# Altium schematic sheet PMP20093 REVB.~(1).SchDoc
size 431 x 279 mm; Date: Not shown in title block; ApprovedBy: Not shown in title block; CheckedBy: Not shown in title block; Author: Not shown in title block; CompanyName: Not shown in title block; Engineer: Not shown in title block; Organization: Not shown in title block; Address1: Not shown in title block; Address2: Not shown in title block; Address3: Not shown in title block; Address4: Not shown in title block; DocumentNumber: 1; Revision: Use project parameter SCH_Rev; SheetNumber: 2; SheetTotal: 3; PageSetup: Record=PageOptions¦CenterHorizontal=True¦CenterVertical=True¦PrintScale=1.00¦XCorrection=1.00¦YCorrection=1.00¦PrintKind=0¦BorderSize=5000000¦LeftOffset=0¦BottomOffset=0¦Orientation=2¦PaperLength=1000¦PaperWidth=1000¦Scale=100¦PaperSource=15¦PrintQuality=600¦MediaType=1¦DitherType=10¦PaperKind=Letter¦PrintScaleMode=1
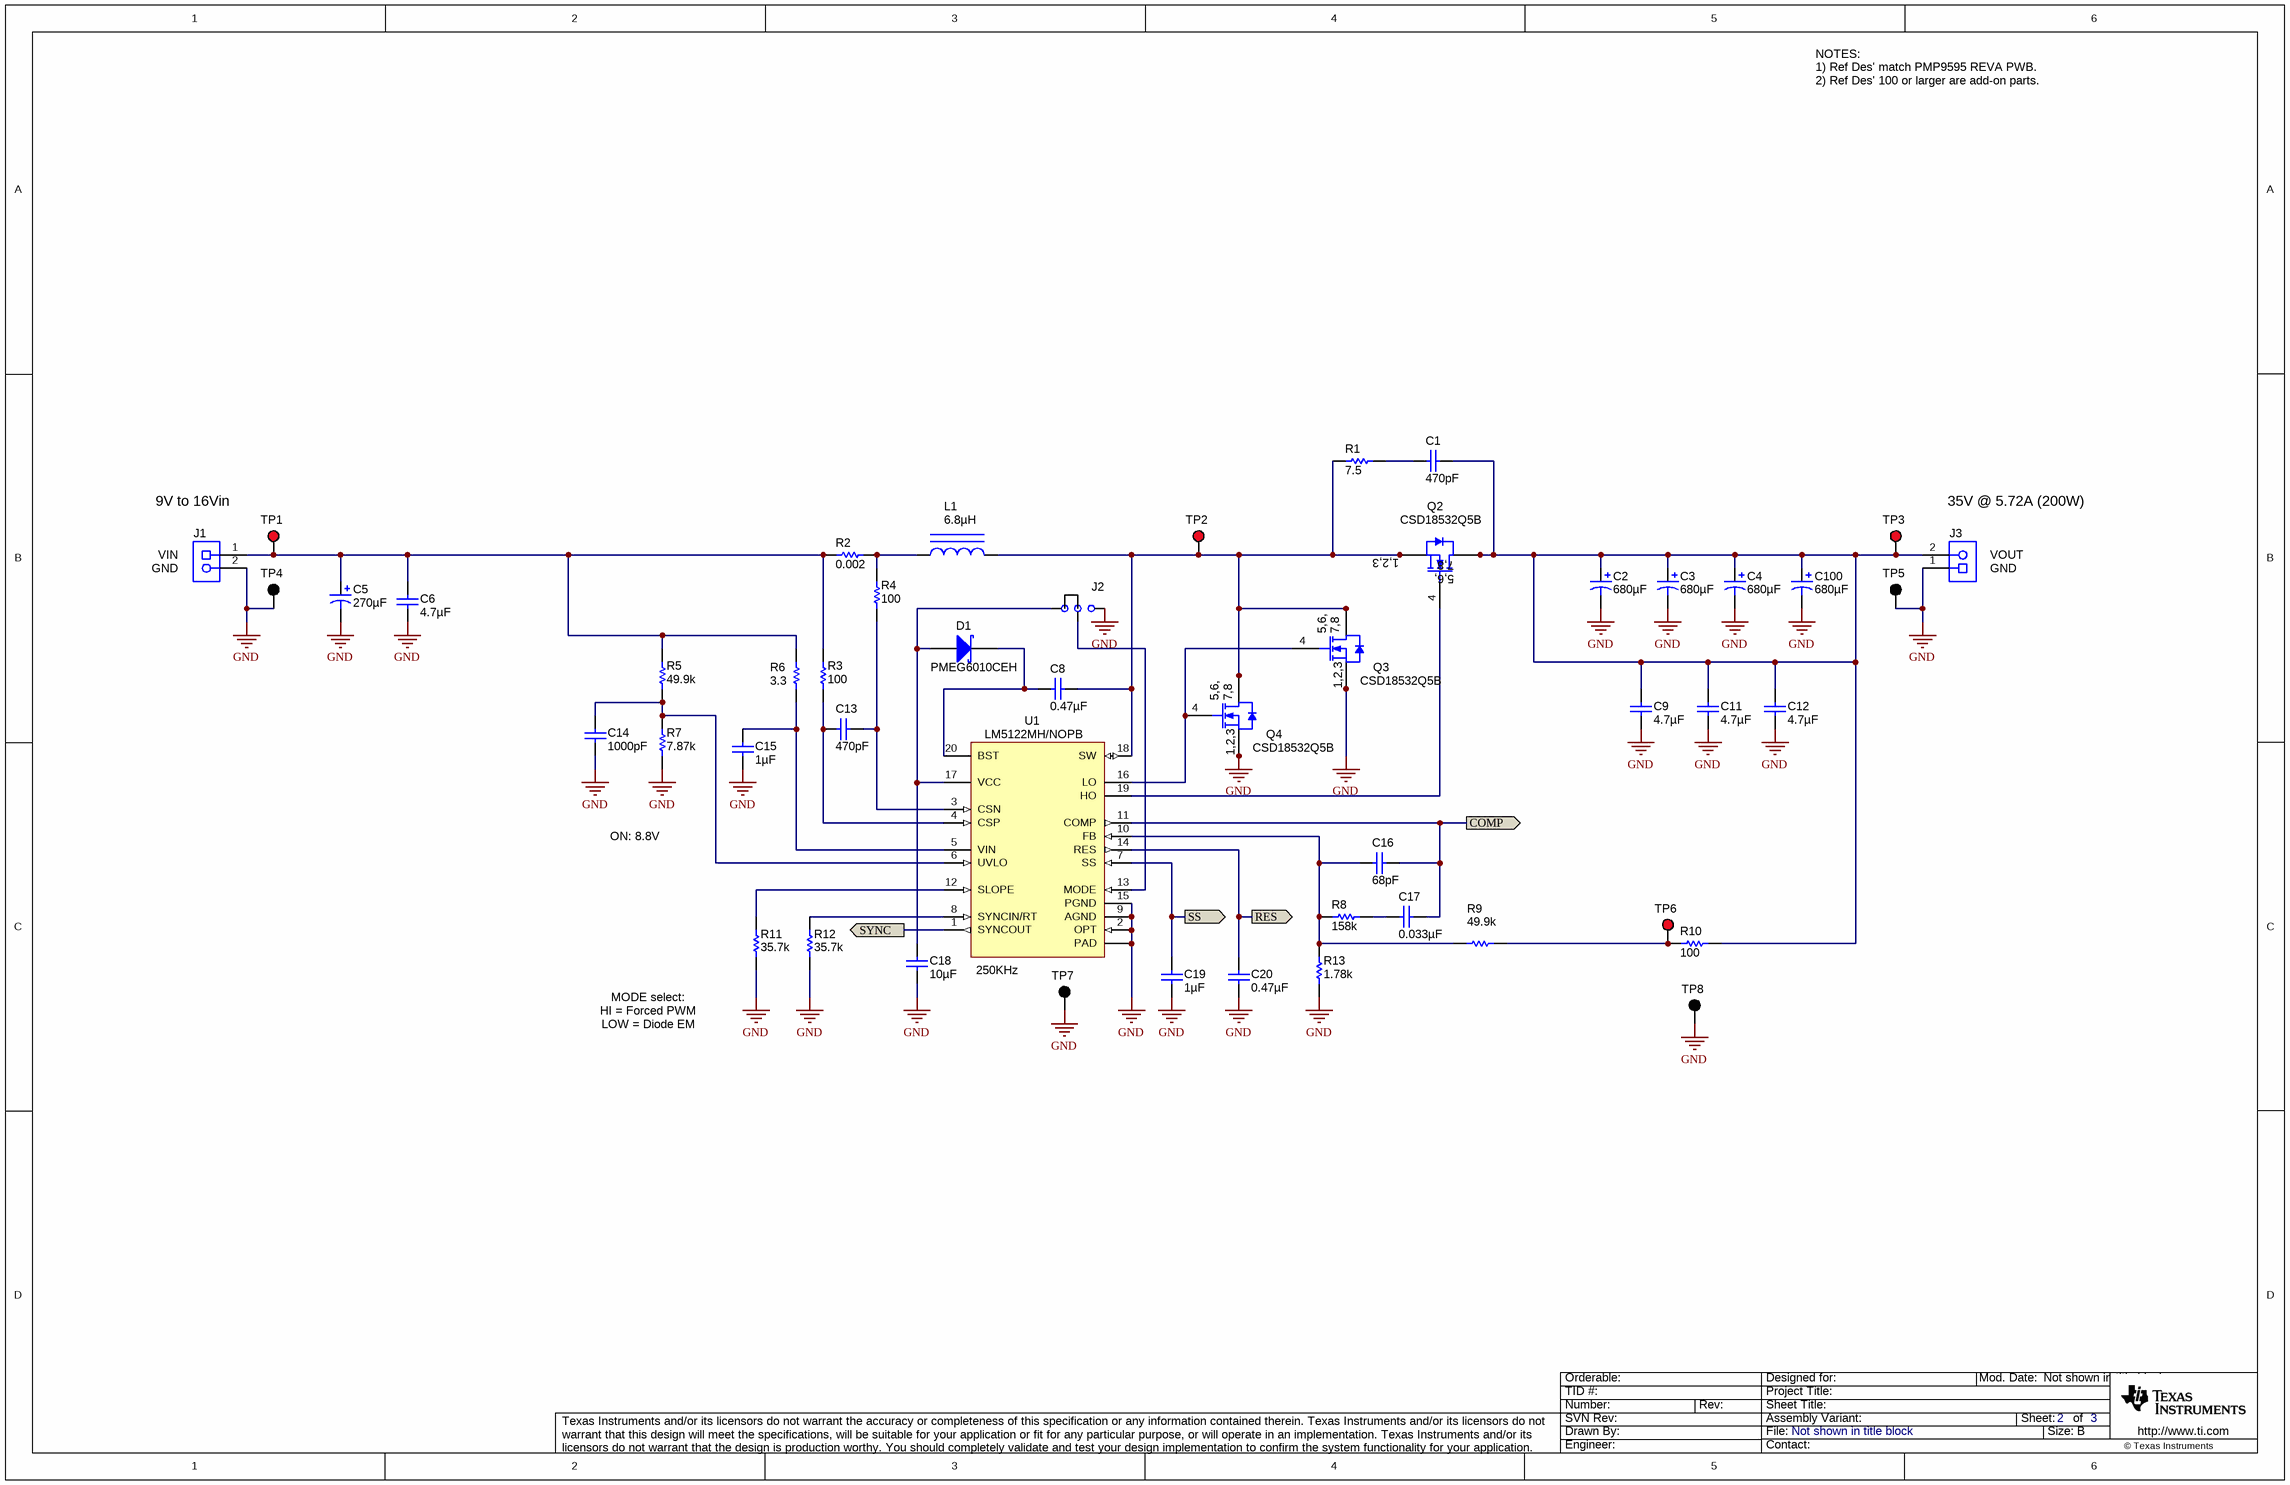
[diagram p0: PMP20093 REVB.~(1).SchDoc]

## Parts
C1  ValueDisplayed: 470pF  [0603]  (hidden comment: C1608C0G1H471J)
C2  ValueDisplayed: 680µF  [ZL_1250x2500]  (hidden comment: 50ZL680MEFC12.5X25)
C3  ValueDisplayed: 680µF  [ZL_1250x2500]  (hidden comment: 50ZL680MEFC12.5X25)
C4  ValueDisplayed: 680µF  [ZL_1250x2500]  (hidden comment: 50ZL680MEFC12.5X25)
C5  ValueDisplayed: 270µF  [SM_RADIAL_10BMM]  (hidden comment: EEHZA1V271P)
C6  ValueDisplayed: 4.7µF  [1210]  (hidden comment: GRM32ER71H475KA88L)
C8  ValueDisplayed: 0.47µF  [0603]  (hidden comment: GRM188R71E474KA12D)
C9  ValueDisplayed: 4.7µF  [1210]  (hidden comment: GRM32ER71H475KA88L)
C11  ValueDisplayed: 4.7µF  [1210]  (hidden comment: GRM32ER71H475KA88L)
C12  ValueDisplayed: 4.7µF  [1210]  (hidden comment: GRM32ER71H475KA88L)
C13  ValueDisplayed: 470pF  [0603]  (hidden comment: C1608C0G1H471J)
C14  ValueDisplayed: 1000pF  [0603]  (hidden comment: GRM188R71H102KA01D)
C15  ValueDisplayed: 1µF  [1206]  (hidden comment: C3216X7R1H105K)
C16  ValueDisplayed: 68pF  [0603]  (hidden comment: C1608C0G1H680J)
C17  ValueDisplayed: 0.033µF  [0603]  (hidden comment: C1608X7R1H333K)
C18  ValueDisplayed: 10µF  [1206]  (hidden comment: C3216X7R1E106K)
C19  ValueDisplayed: 1µF  [0603]  (hidden comment: C1608X7R1E105K080AB)
C20  ValueDisplayed: 0.47µF  [0603]  (hidden comment: GRM188R71E474KA12D)
C100  ValueDisplayed: 680µF  [ZL_1250x2500]  (hidden comment: 50ZL680MEFC12.5X25)
D1  PMEG6010CEH  [SOD-123F]
J1  ED120/2DS  [CONN_ED120-2DS]  (value not drawn)
J2  JUMPER_3X100MIL  [HDR100_1X3]  (value not drawn)
J3  ED120/2DS  [CONN_ED120-2DS]  (value not drawn)
L1  ValueDisplayed: 6.8µH  [IHLP8787MZ]  (hidden comment: IHLP8787MZER6R8M5A)
Q2  CSD18532Q5B  [TRANS_NexFET_Q5B]
Q3  CSD18532Q5B  [TRANS_NexFET_Q5B]
Q4  CSD18532Q5B  [TRANS_NexFET_Q5B]
R1  value 7.5  [2010M]  (hidden comment: CRM2010-JW-7R5ELF)
R2  value 0.002  [2512]  (hidden comment: CSNL2512FT2L00)
R3  value 100  [0603_HV]  (hidden comment: ERJ-3GEY0R00V)
R4  value 100  [0603_HV]  (hidden comment: ERJ-3GEY0R00V)
R5  value 49.9k  [0603]  (hidden comment: CRCW060349K9FKEA)
R6  value 3.3  [0603_HV]  (hidden comment: CRCW06033R30JNEA)
R7  ValueDisplayed: 7.87k  [0603]  (hidden comment: CRCW06037K87FKEA)
R8  ValueDisplayed: 158k  [0603]  (hidden comment: CRCW0603158KFKEA)
R9  value 49.9k  [0603]  (hidden comment: CRCW060349K9FKEA)
R10  value 100  [0603]  (hidden comment: CRCW0603100RFKEA)
R11  ValueDisplayed: 35.7k  [0603]  (hidden comment: CRCW060335K7FKEA)
R12  ValueDisplayed: 35.7k  [0603]  (hidden comment: CRCW060335K7FKEA)
R13  ValueDisplayed: 1.78k  [0603]  (hidden comment: CRCW06031K78FKEA)
TP1  5010  [Keystone5010]  (value not drawn)
TP2  5010  [Keystone5010]  (value not drawn)
TP3  5010  [Keystone5010]  (value not drawn)
TP4  5011  [Keystone5011]  (value not drawn)
TP5  5011  [Keystone5011]  (value not drawn)
TP6  5010  [Keystone5010]  (value not drawn)
TP7  5011  [Keystone5011]  (value not drawn)
TP8  5011  [Keystone5011]  (value not drawn)
U1  LM5122MH/NOPB  [PWP0020A_N]

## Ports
COMP, RES, SS, SYNC

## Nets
GND: C2.2(-) C3.2(-) C4.2(-) C5.2(-) C6.2 C9.2 C11.2 C12.2 C14.2 C15.2 C18.2 C19.2 C20.1 C100.2(-) J1.2 J2.1 J3.1 Q3.1(S) Q3.2(S) Q3.3(S) Q4.1(S) Q4.2(S) Q4.3(S) R7.1 R11.1 R12.1 R13.1 TP4.1 TP5.1 TP7.1 TP8.1 U1.2(OPT) U1.9(AGND) U1.15(PGND) U1.21(PAD)
COMP: C16.2 C17.2 U1.11(COMP) ; port COMP
RES: C20.2 U1.14(RES) ; port RES
SS: C19.1 U1.7(SS) ; port SS
SYNC: U1.1(SYNCOUT) ; port SYNC
NetC1_1: C1.1 C2.1(+) C3.1(+) C4.1(+) C9.1 C11.1 C12.1 C100.1(+) J3.2 Q2.5(D) Q2.6(D) Q2.7(D) Q2.8(D) R10.2 TP3.1
NetC1_2: C1.2 R1.2
NetC5_1: C5.1(+) C6.1 J1.1 R2.1 R3.2 R5.2 R6.1 TP1.1
NetC8_1: C8.1 D1.1(K) U1.20(BST)
NetC8_2: C8.2 L1.2 Q2.1(S) Q2.2(S) Q2.3(S) Q3.5(D) Q3.6(D) Q3.7(D) Q3.8(D) Q4.5(D) Q4.6(D) Q4.7(D) Q4.8(D) R1.1 TP2.1 U1.18(SW)
NetC13_1: C13.1 R4.1 U1.3(CSN)
NetC13_2: C13.2 R3.1 U1.4(CSP)
NetC14_1: C14.1 R5.1 R7.2 U1.6(UVLO)
NetC15_1: C15.1 R6.2 U1.5(VIN)
NetC16_1: C16.1 R8.1 R9.1 R13.2 U1.10(FB)
NetC17_1: C17.1 R8.2
NetC18_1: C18.1 D1.2(A) J2.3 U1.17(VCC)
NetJ2_2: J2.2 U1.13(MODE)
NetL1_1: L1.1 R2.2 R4.2
NetQ2_4: Q2.4(G) U1.19(HO)
NetQ3_4: Q3.4(G) Q4.4(G) U1.16(LO)
NetR9_2: R9.2 R10.1 TP6.1
NetR11_2: R11.2 U1.12(SLOPE)
NetR12_2: R12.2 U1.8(SYNCIN/RT)

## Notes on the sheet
- NOTES:
  1) Ref Des' match PMP9595 REVA PWB.
  2) Ref Des' 100 or larger are add-on parts.
- 9V to 16Vin
- 35V @ 5.72A (200W)
- (near J1) VIN
- (near J1) GND
- (near J3) VOUT
- (near J3) GND
- ON: 8.8V
- (near U1) 250KHz
- MODE select:
- HI = Forced PWM
- LOW = Diode EM

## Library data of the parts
C1 C13 = C1608C0G1H471J: CAP, CERM, 470pF, 50V, +/-5%, C0G/NP0, 0603; Manufacturer: TDK; Polarized: N; CompType: Capacitor; U/M: EA; Cap_F: 0.00000000047; Tolerance_%: 5; ESR_Ohm: 0.0922; Value1: 0.0922 ohm; VDC_V: 50; TaMin_C: -55; TaMax_C: 125
C2-C4 C100 = 50ZL560MEFC12.5X25: CAP, AL, 680 µF, 50 V, +/- 20%, 2.86A, 0.021 ohm, TH; Manufacturer: Rubycon; Polarized: Y; CompType: Capacitor; Value: 680uF; U/M: EA; Cap_F: 0.00056; Tolerance_%: 20; VDC_V: 50; Value2: 50V; ESR_ohm: 0.023; IRMS_A: 2.41; TaMin_C: -40; TaMax_C: 105; Cap_Case: 12.5x25mm; AEC Category: Q200; AEC Qualified: N
C5 = EEHZA1V271P: CAP, Polymer Hybrid, 270 µF, 35 V, +/- 20%, 20 ohm, 10x10 SMD; Manufacturer: Panasonic; Polarized: Y; CompType: Capacitor; Value: 270uF; U/M: EA; Cap_F: 0.00027; Tolerance_%: 20; Value1: 20 ohm; VDC_V: 35; Value2: 35V; IRMS_A: 2.5; TaMin_C: -55; TaMax_C: 105; AEC Category: Q200
C6 C9 C11 C12 = GRM32ER71H475KA88L: CAP, CERM, 4.7uF, 50V, +/-10%, X7R, 1210; Manufacturer: MuRata; Polarized: N; CompType: Capacitor; U/M: EA; Cap_F: 0.0000047; Tolerance_%: 10; ESR_Ohm: 0.002; Value1: 0.002 ohm; VDC_V: 50; TaMin_C: -55; TaMax_C: 125
C8 C20 = GRM188R71E474KA12D: CAP, CERM, 0.47uF, 25V, +/-10%, X7R, 0603; Manufacturer: MuRata; Polarized: N; CompType: Capacitor; U/M: EA; Cap_F: 0.00000047; Tolerance_%: 10; Value1: Unknown; VDC_V: 25; TaMin_C: -55; TaMax_C: 125
C14 = GRM188R71H102KA01D: CAP, CERM, 1000pF, 50V, +/-10%, X7R, 0603; Manufacturer: MuRata; Polarized: N; CompType: Capacitor; U/M: EA; Cap_F: 0.000000001; Tolerance_%: 10; Value1: Unknown; VDC_V: 50; TaMin_C: -55; TaMax_C: 125
C15 = C3216X7R1H105K: CAP, CERM, 1 µF, 50 V, +/- 10%, X7R, 1206; Manufacturer: TDK; Polarized: N; CompType: Capacitor; Value: 1uF; U/M: EA; Cap_F: 0.000001; Tolerance_%: 10; ESR_ohm: 0.01; Value1: 0.01 ohm; VDC_V: 50; Value2: 50V; IRMS_A: 3.2; TaMin_C: -55; TaMax_C: 125; AEC Category: Q200
C16 = C1608C0G1H680J: CAP, CERM, 68 pF, 50 V, +/- 5%, C0G/NP0, 0603; Manufacturer: TDK; Polarized: N; CompType: Capacitor; Value: 68pF; U/M: EA; Cap_F: 0.000000000068; Tolerance_%: 5; ESR_ohm: 0.1724; Value1: 0.1724 ohm; VDC_V: 50; Value2: 50V; TaMin_C: -55; TaMax_C: 125; AEC Category: Q200
C17 = C1608X7R1H223K: CAP, CERM, 0.033 µF, 50 V, +/- 10%, X7R, 0603; Manufacturer: TDK; Polarized: N; CompType: Capacitor; Value: 0.033uF; U/M: EA; Cap_F: 0.000000022; Tolerance_%: 10; ESR_ohm: 0.0383; Value1: 0.0383 ohm; VDC_V: 50; Value2: 50V; TaMin_C: -55; TaMax_C: 125; AEC Category: Q200
C18 = C3216X7R1C475K: CAP, CERM, 10uF, 25V, +/-10%, X7R, 1206; Manufacturer: TDK; Polarized: N; CompType: Capacitor; U/M: EA; Cap_F: 0.0000047; Tolerance_%: 10; ESR_Ohm: 0.0036; Value1: 0.0036 ohm; VDC_V: 25; IRMS_A: 2; TaMin_C: -55; TaMax_C: 125
C19 = C1608X7R1E105K080AB: CAP, CERM, 1 µF, 25 V, +/- 10%, X7R, 0603; Manufacturer: TDK; Polarized: N; CompType: Capacitor; Value: 1uF; U/M: EA; Cap_F: 0.000001; Tolerance_%: 10; Value1: Unknown; VDC_V: 25; Value2: 25V; TaMin_C: -55; TaMax_C: 125; AEC Category: Q200
D1 = PMEG6010CEH,115: Diode, Schottky, 60V, 1A, SOD-123F; Manufacturer: NXP Semiconductor; U/M: EA; Vf_V: 0.57; Value2: 0.57V; Io_A: 1; Vr_V: 60; TJmax_C: 150
J1 J3 = ED120/2DS: TERMINAL BLOCK, 15A, VERT 2POS, TH; Manufacturer: On-Shore Technology; SymbolCreator: a0412235; U/M: EA
J2 = JUMPER_3X100MIL: Header, Male 3-pin, 100mil spacing,; Manufacturer: Sullins; PartNumber: PEC03SAAN; area: 30000; Value: PEC03SAAN
L1 = IHLP8787MZER100M5A: Inductor, Shielded, 6.8 µH, 36A, 0.00284 ohm, AEC-Q200 Grade 0, SMD; Manufacturer: Vishay-Dale; Value: 6.8uH; AEC Category: Q200; AEC Qualified: Y; AEC Grade: 0
Q2-Q4 = CSD18532Q5B: MOSFET, N-CH, 60V, 172A, SON 5x6mm; Manufacturer: Texas Instruments; Alternate Manufacturer: None; U/M: EA; ChType: N; VdsMax_V: 60; Value1: 3.3 ohm; Rdson45_Ohm: 3.3; Value2: 27 nC; QgTyp_nC: 27; Vgs_V: 1.6; IdsMax_A: 172
R1 = CRM2010-JW-7R5ELF: RES, 7.5 ohm, 5%, 1W, 2010; Manufacturer: Bourns; CompType: Resistor; Value_Code: 7R50; Tolerance_%: 5; Power_W: 1; VDC_V: 3; TempCo: 100 ppm/C; EIA_Code: E24; U/M: EA
R2 = CSNL2512FT2L00: RES, 0.002 ohm, 1%, 2W, 2512; Manufacturer: Stackpole Electronics Inc; CompType: Resistor; Value_Code: R002; Tolerance_%: 1; Power_W: 2; VDC_V: 200; TempCo: 50 ppm/C; U/M: EA
R3 R4 = ERJ-3GEY0R00V: RES, 0 ohm, 5%, 0.1W, 0603; Manufacturer: Panasonic; CompType: Resistor; Res_ohm: 0; Value_Code: 0000; Tolerance_%: 5; Power_W: 0.1; VDC_V: 50; TempCo: 600 ppm/C; EIA_Code: E24; U/M: EA
R5 R9 = CRCW060349K9FKEA: RES, 49.9k ohm, 1%, 0.1W, 0603; Manufacturer: Vishay-Dale; CompType: Resistor; Res_ohm: 49900; Value_Code: 49k9; Tolerance_%: 1; Power_W: 0.1; VDC_V: 75; TempCo: 100 ppm/C; EIA_Code: E96; U/M: EA
R6 = CRCW06033R30JNEA: RES, 3.3 ohm, 5%, 0.1W, 0603; Manufacturer: Vishay-Dale; CompType: Resistor; Value_Code: 3R30; Tolerance_%: 5; Power_W: 0.1; VDC_V: 75; TempCo: 200 ppm/C; EIA_Code: E24; U/M: EA
R7 = CRCW06037K87FKEA: RES, 7.87 k, 1%, 0.1 W, 0603; Manufacturer: Vishay-Dale; CompType: Resistor; Value: 7.87k; Res_ohm: 7870; Value_Code: 7k87; Tolerance_%: 1; Power_W: 0.1; Value2: 0.1W; VDC_V: 75; TempCo: 100 ppm/C; EIA_Code: E96; U/M: EA; AEC Category: Q200
R8 = CRCW0603158KFKEA: RES, 158 k, 1%, 0.1 W, 0603; Manufacturer: Vishay-Dale; CompType: Resistor; Value: 158k; Res_ohm: 158000; Tolerance_%: 1; Power_W: 0.1; Value2: 0.1W; VDC_V: 75; TempCo: 100 ppm/C; EIA_Code: E96; U/M: EA; AEC Category: Q200
R10 = CRCW0603100RFKEA: RES, 100 ohm, 1%, 0.1W, 0603; Manufacturer: Vishay-Dale; CompType: Resistor; Value_Code: 100R; Tolerance_%: 1; Power_W: 0.1; VDC_V: 75; TempCo: 100 ppm/C; EIA_Code: E96; U/M: EA
R11 R12 = CRCW060335K7FKEA: RES, 35.7 k, 1%, 0.1 W, 0603; Manufacturer: Vishay-Dale; CompType: Resistor; Value: 35.7k; Res_ohm: 35700; Value_Code: 35k7; Tolerance_%: 1; Power_W: 0.1; Value2: 0.1W; VDC_V: 75; TempCo: 100 ppm/C; EIA_Code: E96; U/M: EA; AEC Category: Q200
R13 = CRCW06031K78FKEA: RES, 1.78 k, 1%, 0.1 W, 0603; Manufacturer: Vishay-Dale; CompType: Resistor; Value: 1.78k; Res_ohm: 1780; Value_Code: 1k78; Tolerance_%: 1; Power_W: 0.1; Value2: 0.1W; VDC_V: 75; TempCo: 100 ppm/C; EIA_Code: E96; U/M: EA; AEC Category: Q200
TP1-TP3 TP6 = 5010: Test Point, Multipurpose, Red, TH; Manufacturer: Keystone; CompType: Test Point Loop; U/M: EA
TP4 TP5 TP7 TP8 = 5011: Test Point, Multipurpose, Black, TH; Manufacturer: Keystone; CompType: Test Point Loop; U/M: EA
U1 = LM5122MH/NOPB: Wide Input Synchronous Boost Controller with Multiple Phase Capability, PWP0020A; Alternate Manufacturer: None; Manufacturer: Texas Instruments; SymbolCreator: a0411947; CompType: IC; U/M: EA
